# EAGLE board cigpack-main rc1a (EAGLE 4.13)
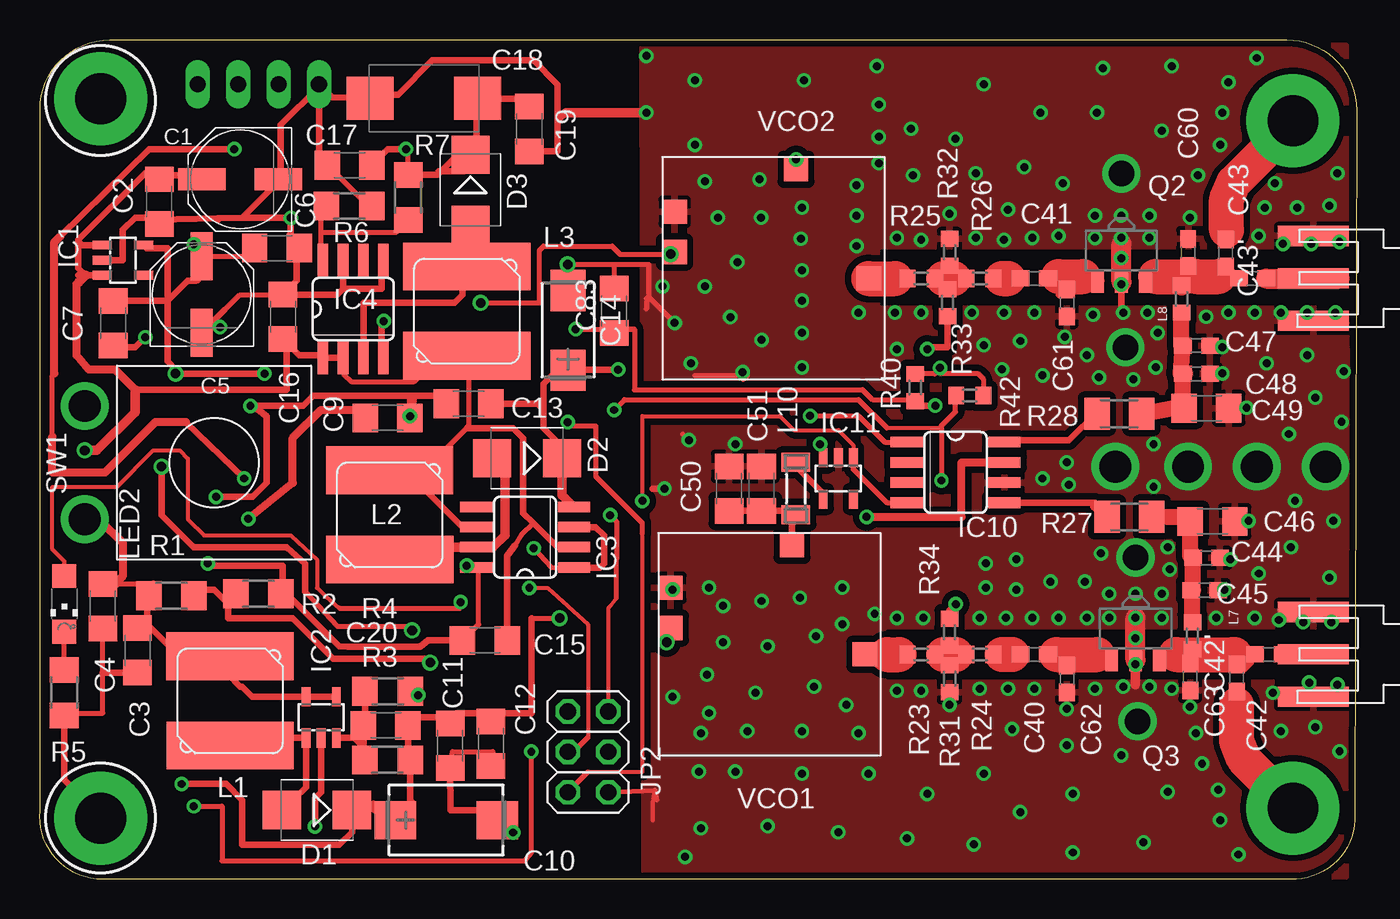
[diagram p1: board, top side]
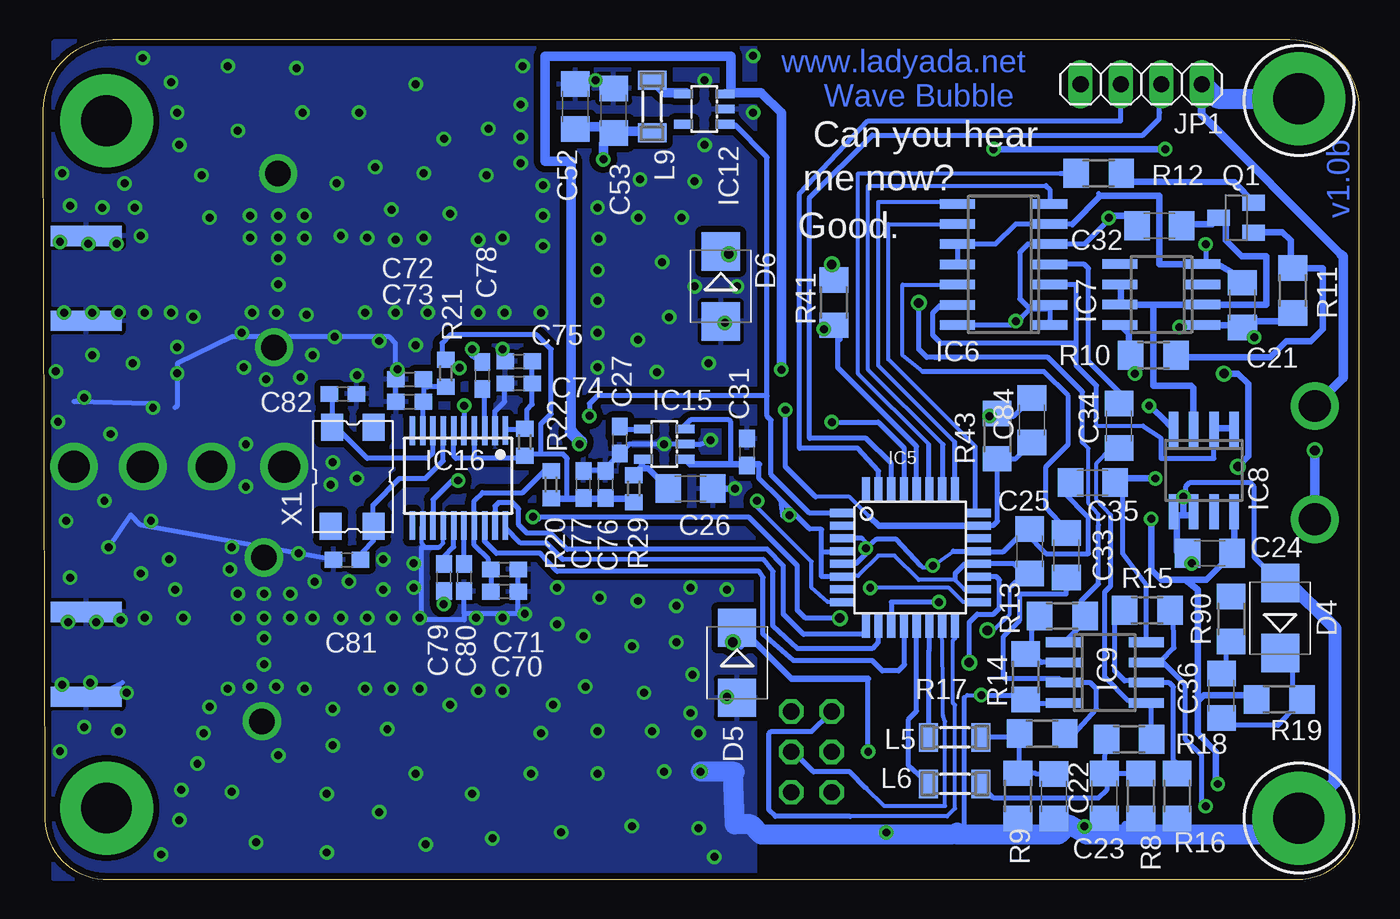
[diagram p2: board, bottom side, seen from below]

Size 82.75 x 52.73 mm. Coordinates in mm from the lower left corner, seen from the top.
Outline: 3.57,0 arc-90 0.02,4.31 0.02,48.34 arc-90 4.4,52.73 78.36,52.73 arc-90 82.75,48.32 82.65,4.08 arc-90 78.96,0 3.57,0
Copper layers (1*16): Top 0.035mm / dielectric 1.5mm / Bottom 0.035mm
Design rules "default": minimum track width 10mil, minimum drill 19mil, track to track 10mil, track to pad 10mil, pad to pad 10mil, via to via 10mil, smd to smd 0mil, copper to edge 10mil, drill to drill 8mil, minimum pad ring 10mil, minimum via ring 8mil, stop-mask expansion 4mil, vias tented up to drill 0mil, thermal gap 10mil

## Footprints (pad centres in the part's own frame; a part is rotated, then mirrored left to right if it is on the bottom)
PANASONIC_D = smd 3 x 1.4: + 2.4,0; - -2.4,0
C1206 = smd 1.6 x 1.8: 1 -1.4,0; 2 1.4,0
CT7343 = smd 2.6 x 2.4: + 3.2,0; - -3.2,0
CT6032 = smd 2.6 x 2.2: + 2.5,0; - -2.5,0
D/7343-31W = smd 2.95 x 2.7: + 3.375,0; - -3.375,0
C0603 = smd 1.1 x 1: 1 -0.85,0; 2 0.85,0
SMB = smd 2.4 x 2.4: A 2.2,0; C -2.2,0
SOT23-5L = smd 0.55 x 1.2: 1 -0.95,-1.3; 2 0,-1.3; 3 0.95,-1.3; 4 0.95,1.3; 5 -0.95,1.3
SO08 = smd 0.66 x 2.032: 1 -1.905,-3.073; 2 -0.635,-3.073; 3 0.635,-3.073; 4 1.905,-3.073; 5 1.905,3.073; 6 0.635,3.073; 7 -0.635,3.073; 8 -1.905,3.073
TQFP32-08 = smd 1.524 x 0.508: 1 -4.293,2.8; 2 -4.293,2; 3 -4.293,1.2; 4 -4.293,0.4; 5 -4.293,-0.4; 6 -4.293,-1.2; 7 -4.293,-2; 8 -4.293,-2.8; 17 4.293,-2.8; 18 4.293,-2; 19 4.293,-1.2; 20 4.293,-0.4; 21 4.293,0.4; 22 4.293,1.2; 23 4.293,2; 24 4.293,2.8 | smd 0.508 x 1.524: 9 -2.8,-4.293; 10 -2,-4.293; 11 -1.2,-4.293; 12 -0.4,-4.293; 13 0.4,-4.293; 14 1.2,-4.293; 15 2,-4.293; 16 2.8,-4.293; 25 2.8,4.293; 26 2,4.293; 27 1.2,4.293; 28 0.4,4.293; 29 -0.4,4.293; 30 -1.2,4.293; 31 -2,4.293; 32 -2.8,4.293
SO14 = smd 0.6 x 2.2: 1 -3.81,-2.9; 2 -2.54,-2.9; 3 -1.27,-2.9; 4 0,-2.9; 5 1.27,-2.9; 6 2.54,-2.9; 7 3.81,-2.9; 8 3.81,2.9; 9 2.54,2.9; 10 1.27,2.9; 11 0,2.9; 12 -1.27,2.9; 13 -2.54,2.9; 14 -3.81,2.9
SO08' = smd 0.6 x 2.2: 1 -1.905,-2.6; 2 -0.635,-2.6; 3 0.635,-2.6; 4 1.905,-2.6; 5 1.905,2.6; 6 0.635,2.6; 7 -0.635,2.6; 8 -1.905,2.6
TSSOP-20 = smd 0.35 x 1.8: 1 -2.835,-3.023; 2 -2.195,-2.999; 3 -1.545,-2.999; 4 -0.895,-2.999; 5 -0.245,-2.999; 6 0.405,-2.999; 7 1.055,-2.999; 8 1.705,-2.999; 9 2.355,-2.999; 10 3.005,-2.999; 11 3.005,2.951; 12 2.355,2.951; 13 1.705,2.951; 14 1.055,2.951; 15 0.405,2.951; 16 -0.245,2.951; 17 -0.895,2.951; 18 -1.545,2.951; 19 -2.195,2.951; 20 -2.845,2.951
1X04 = drill 1.016 long: 1 -3.81,0; 2 -1.27,0; 3 1.27,0; 4 3.81,0
2X03 = drill 1.016 octagon: 1 -2.54,-1.27; 2 -2.54,1.27; 3 0,-1.27; 4 0,1.27; 5 2.54,-1.27; 6 2.54,1.27
CDRH6D28 = smd 3 x 8: L1 -2.8,-0.008; L2 2.8,0.008
SM-1206 = smd 1.2 x 1.8: 1 -1.65,0; 2 1.65,0
0603 = smd 1 x 1.1: 1 -0.875,0.025; 2 0.825,0.025
CHIPLED_1206 = smd 1.5 x 1.5: A 0,-1.75; C 0,1.75
SOT23-BEC = smd 1 x 1.4: B -0.95,-1.1; C 0,1.1; E 0.95,-1.1
SOT89 = smd 0.8 x 1.4: 1 -1.499,-1.981; 2 0,-1.981; 3 1.499,-1.981
R1206 = smd 1.6 x 1.803: 1 -1.422,0; 2 1.422,0
R0603 = smd 1 x 1.1: 1 -0.85,0; 2 0.85,0
M1206 = smd 1.6 x 2: 1 -1.4,0; 2 1.4,0
JUDCOSPST = drill 2 round: P 3.556,-8.128; T -3.556,-8.128
SMA-ANTENNA = smd 1.27 x 4.445: COND 0,-2.794; GND3 -2.667,-2.794; GND4 2.667,-2.794 | smd 1.27 x 4.445 bottom: GND -2.667,-2.794; GND2 2.667,-2.794
MINICIRCUITS_KG = smd 1.524 x 1.524: P$1 3.429,0.762; P$2 5.969,0.762; P$10 7.62,12.954; P$14 0.762,8.382
ABMM = smd 1.7 x 1.4: NC 3.1,-1.3; NC2 -3.1,1.4; X1 -3.1,-1.3; X2 3.1,1.3

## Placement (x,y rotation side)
C1  100uF/6.3  [PANASONIC_D]  12.59,43.97 180 top
C2  .1uF  [C1206]  7.51,42.57 270 top
C3  .1uF  [C1206]  6.14,14.37 270 top
C4  1.0uF  [C1206]  3.97,17.15 270 top
C5  100uF/4V  [PANASONIC_D]  10.18,36.73 90 top
C6  1uF  [C1206]  14.9,39.64 0 top
C7  .1uF  [C1206]  4.61,34.92 270 top
C9  .1uF  [C1206]  21.86,28.98 0 top
C10  100uF/10V  [CT7343]  25.55,3.71 180 top
C11  .1uF  [C1206]  25.79,8.38 270 top
C12  1.0uF  [C1206]  28.35,8.52 270 top
C13  .1uF  [C1206]  26.94,29.87 180 top
C14  68uF/16V  [CT6032]  33.19,34.47 270 top
C15  1.0uF  [C1206]  27.97,15 180 top
C16  .1uF  [C1206]  15.28,35.33 90 top
C17  .1uF  [C1206]  19.47,44.85 180 top
C18  22uF/35V  [D/7343-31W]  24.15,49.05 0 top
C19  1.0uF  [C1206]  30.76,47.13 270 top
C20  160pF  [C1206]  21.75,9.66 180 top
C21  .1uF  [C1206]  7.38,36.07 270 bottom
C22  4.7uF  [C1206]  19.22,5.2 270 bottom
C23  4.7uF  [C1206]  16.05,5.23 270 bottom
C24  .1uF  [C1206]  9.42,20.47 180 bottom
C25  .1uF  [C1206]  20.74,20.59 90 bottom
C26  1.0uF  [C1206]  42.06,24.54 0 bottom
C27  .01uF  [C0603]  46.5,27.58 270 bottom
C31  .1uF  [C0603]  38.5,26.82 90 bottom
C32  .1uF  [C1206]  12.59,41.05 180 bottom
C33  4.7uF  [C1206]  18.43,20.34 270 bottom
C34  4.7uF  [C1206]  15.13,28.47 270 bottom
C35  .1uF  [C1206]  16.78,24.92 180 bottom
C36  .47uF  [C1206]  8.69,11.52 270 bottom
C40  68pF  [C0603]  62.5,14.12 180 top
C41  100pF  [C0603]  62.5,37.74 180 top
C42  68pF  [C0603]  77.23,14.12 180 top
C42'  68pF  [C0603]  75.22,12.65 90 top
C43  100pF  [C0603]  76.22,37.74 180 top
C43'  100pF  [C0603]  74.52,39.33 270 top
C44  1000pF  [C0603]  73.32,20.19 180 top
C45  22pF  [C0603]  73.19,18.16 180 top
C46  .1uF  [C1206]  73.7,22.47 180 top
C47  1000pF  [C0603]  72.68,33.52 180 top
C48  68pF  [C0603]  72.68,31.74 180 top
C49  .1uF  [C1206]  73.32,29.59 180 top
C50  1uF  [C1206]  43.33,24.54 90 top
C51  0.1uF  [C1206]  45.36,24.54 90 top
C52  1uF  [C1206]  49.29,48.54 90 bottom
C53  0.1uF  [C1206]  46.88,48.29 90 bottom
C60  3.9pF  [C0603]  72.16,39.38 90 top
C61  5.6pF  [C0603]  64.54,36.2 270 top
C62  0pF  [C0603]  64.54,12.58 270 top
C63  1.0pF  [C0603]  72.29,12.71 270 top
C70  .01uF  [C0603]  53.74,18.06 0 bottom
C71  100pf  [C0603]  53.74,19.46 0 bottom
C72  100pf  [C0603]  59.71,31.39 180 bottom
C73  .01uF  [C0603]  59.71,30 180 bottom
C74  100pf  [C0603]  52.85,31.14 180 bottom
C75  .01uF  [C0603]  52.85,32.54 180 bottom
C76  .1uF  [C0603]  47.39,24.79 90 bottom
C77  4.7uF  [C0603]  48.79,24.79 90 bottom
C78  100pf  [C0603]  55.14,31.65 270 bottom
C79  100pf  [C0603]  57.55,18.95 90 bottom
C80  100pf  [C0603]  56.28,18.95 270 bottom
C81  20pF  [C0603]  63.64,20.07 180 bottom
C82  20pF  [C0603]  63.89,30.48 0 bottom
C83  0.1uF  [C1206]  36.1,35.7 90 top
C84  0.1uF  [C1206]  20.6,28.84 90 bottom
D1  1N5817  [SMB]  17.42,4.34 180 top
D2  1N5817  [SMB]  30.63,26.44 180 top
D3  1N5817  [SMB]  27.06,43.31 270 top
D4  1N5235  [SMB]  5,16.4 90 bottom
D5  1N5817  [SMB]  39.13,13.59 270 bottom
D6  1N5817  [SMB]  40.15,37.24 270 bottom
IC1  TPS79333  [SOT23-5L]  5.23,38.89 270 top
IC2  LM2733  [SOT23-5L]  17.68,10.17 0 top
IC3  LT1301  [SO08]  30.5,21.49 90 top
IC4  LT1173CS  [SO08]  19.7,35.81 0 top
IC5  ATMEGA48-20A  [TQFP32-08]  28.24,20.21 0 bottom
IC6  AD8402  [SO14]  22.38,38.62 90 bottom
IC7  NE555D  [SO08']  12.46,36.73 90 bottom
IC8  LM358D  [SO08']  9.8,25.68 180 bottom
IC9  LM358D  [SO08']  16.02,12.98 270 bottom
IC10  MIC2506BM  [SO08]  57.55,25.55 270 top
IC11  MIC2514  [SOT23-5L]  50.18,25.17 180 top
IC12  MIC2514  [SOT23-5L]  41.19,48.38 90 bottom
IC15  LP2985  [SOT23-5L]  43.71,27.33 90 bottom
IC16  LMX243X  [TSSOP-20]  56.53,25.17 180 bottom
JP1  [1X04]  13.73,49.94 180 bottom
JP2  [2X03]  34.46,8 270 top
L1  15uH  [CDRH6D28]  11.96,11.2 270 top
L2  33uH  [CDRH6D28]  21.99,22.88 270 top
L3  33uH  [CDRH6D28]  26.84,35.68 90 top
L5  1K  [SM-1206]  25.44,8.91 0 bottom
L6  1K  [SM-1206]  25.44,5.99 0 bottom
L7  22nH  [0603]  72.41,15.27 270 top
L8  33nH  [0603]  71.77,36.47 90 top
L9  0  [SM-1206]  44.47,48.54 90 bottom
L10  0  [SM-1206]  47.52,24.54 270 top
LED2  [CHIPLED_1206]  1.54,17.3 180 top
Q1  3906  [SOT23-BEC]  7.77,41.55 90 bottom
Q2  SXA-389B  [SOT89]  67.97,39.51 0 top
Q3  SXA-389B  [SOT89]  68.86,15.76 0 top
R1  510K  [R1206]  8.27,17.8 180 top
R2  220K  [R1206]  13.73,17.93 180 top
R3  37K  [R1206]  21.86,7.49 0 top
R4  12K  [R1206]  21.86,11.81 180 top
R5  2K  [R1206]  1.54,11.71 270 top
R6  50K  [R1206]  19.44,42.29 180 top
R7  1M  [R1206]  23.16,42.82 90 top
R8  (adj)  [R1206]  13.76,5.23 270 bottom
R9  (adj)  [R1206]  21.48,5.23 270 bottom
R10  10K  [R1206]  12.97,32.92 180 bottom
R11  20K  [R1206]  4.21,36.98 90 bottom
R12  100  [R1206]  16.4,44.35 180 bottom
R13  100K  [R1206]  18.69,16.54 0 bottom
R14  10K  [R1206]  21,12.72 90 bottom
R15  100K  [R1206]  13.35,16.89 0 bottom
R16  10K  [R1206]  11.47,5.23 90 bottom
R17  10K  [R1206]  19.95,9.14 0 bottom
R18  10K  [R1206]  14.5,8.79 0 bottom
R19  2K  [R1206]  5.06,11.29 0 bottom
R20  18  [R0603]  50.82,24.79 90 bottom
R21  18  [R0603]  57.42,31.77 90 bottom
R22  18  [R0603]  52.47,27.46 270 bottom
R23  18  [R0603]  55.39,14.12 180 top
R24  18  [R0603]  59.07,14.12 180 top
R25  18  [R0603]  55.39,37.74 180 top
R26  18  [R0603]  59.07,37.74 180 top
R27  0  [M1206]  68.47,22.76 180 top
R28  0  [M1206]  67.84,29.23 180 top
R29  18  [R0603]  45.61,24.54 270 bottom
R31  0  [R0603]  57.18,12.58 270 top
R32  68  [R0603]  57.18,39.38 90 top
R33  50  [R0603]  57.04,36.22 270 top
R34  50  [R0603]  57.17,15.52 90 top
R40  10k  [R0603]  55.01,30.89 270 top
R41  10k  [R1206]  33.04,36.22 90 bottom
R42  10k  [R0603]  58.44,30.38 180 top
R43  10k  [R1206]  22.78,27.83 270 bottom
R90  100K  [R1206]  8.08,16.34 270 bottom
SW1  SPST  [JUDCOSPST]  10.95,26.17 270 top
U$8  SMAANTENNA  [SMA-ANTENNA]  82.82,37.74 270 top
U$9  SMAANTENNA  [SMA-ANTENNA]  82.82,14.12 270 top
VCO1  ROS2500  [MINICIRCUITS_KG]  38.88,21.74 270 top
VCO2  ROS1200  [MINICIRCUITS_KG]  39.13,45.36 270 top
X1  10.000 MHz  [ABMM]  63.27,25.28 90 bottom

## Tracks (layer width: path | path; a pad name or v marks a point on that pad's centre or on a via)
+6V  (via drill 0.5, 0.6)
  Top 0.305: 30.89,16.39 v32.67,16.39 | 28.86,10.42 28.73,10.04 28.61,10.17 C12.1 | 25.43,10.17 25.56,10.04 25.66,10.17 C11.1 | 23.08,10.23 23.02,10.3 C20.1
  Top 0.406: 30.89,16.39 30.89,10.42 28.86,10.42 26.19,10.42 | 26.19,10.42 25.43,10.17 23.27,10.17 23.08,10.23 23.02,10.17 | 25.92,9.9 25.81,9.92 26.19,10.42 | C20.1 23.15,8.13 23.27,8.01 23.28,8.02 R3.2 23.28,4.97 23.27,4.96 23.36,4.87 C10.+ 20.24,4.72 20.98,4.71 20.97,4.72 D1.C 19.62,2.96 18.82,2.17 12.73,2.17 12.73,4.96 11.71,5.98 v8.92,5.98 | C9.1 20.48,28.97 | C9.1 | 19.7,29.49 19.95,29.49 C9.1
  Top 0.508: v13.1,22.63 15.9,24.9 15.9,27.72 17.67,29.49 19.7,29.49 | IC10.7 57.93,26.19 57.93,22.76 v51.96,22.76
  Top 0.61: C9.1 | C9.1 20.97,28.47 | C9.1 20.21,29.23
  Bottom 0.305: 51.58,22.63 51.83,22.63 51.95,22.74 | 51.95,22.74 v51.96,22.76 | 51.95,22.74 38.38,22.74 35.33,19.69 35.33,16.9 34.83,16.39 v32.67,16.39
  Bottom 0.406: v51.96,22.76 51.96,22.5 | 9.81,11.57 7.1,11.57 R19.1 6.61,11.67 6.63,11.69 6.89,11.44 | 9.81,11.57 10.19,11.31 10.19,18.17 10.95,18.81 | 10.95,18.81 12.47,18.81 13.11,19.44 13.11,21.37 v13.1,22.63 | 8.02,20.44 7.89,20.32 | 8.02,20.44 C24.1 | 7.89,20.32 IC8.8 | 7.89,20.32 7.78,20.2 | 8.02,20.44 9.65,18.81 10.95,18.81 | v8.92,5.98 9.05,5.98 9.05,8.01 10.19,9.15 10.19,11.19 9.81,11.57
+12V  (via drill 0.5)
  Top 0.305: IC11.3 49.17,26.4 v49.04,27.33
  Top 0.406: 32.95,26.57 D2.C 32.83,27.16 31.65,28.33 31.65,29.47 | 28.85,30.25 28.72,30.12 28.47,30.12 | 28.47,30.12 28.34,30.12 | 28.47,30.12 28.47,30.25 | C13.1 28.47,29.99 28.47,30.12 | 28.34,29.98 28.35,29.98 | C13.1 28.34,29.98 | 28.34,29.98 28.22,29.98 | v36.35,32.01 34.57,32.01 32.67,31.99 32.56,31.89 | C13.1 28.45,29.98 | 32.56,31.89 32.41,31.89 31.65,31.12 31.65,29.47 | C14.+ 33.11,31.89 32.56,31.89 | C13.1 28.35,29.86 28.35,29.85 31.27,29.85 31.65,29.47
  Top 0.61: IC3.4 33.55,23.39 32.83,24.11 D2.C
  Bottom 0.61: 49.56,28.08 49.56,45.09 51.21,45.09 51.21,51.7 39.53,51.7 39.53,49.33 IC12.3 39.73,49.33 39.65,49.41 37.62,49.41 36.35,48.14 v36.35,32.01
  Bottom 0.813: 49.56,28.08 48.94,27.46 v49.04,27.33
+24V  (via drill 0.5)
  Top 0.305: C17.1 21.5,45.47 21.63,45.6 | v23.02,45.86 23.12,45.6 R7.2 | 0.92,31.76 0.79,31.63 0.79,27.82
  Top 0.406: v12.85,25.17 9.18,28.71 | 1.29,40.39 6.89,45.86 v12.22,45.86 | R7.2 25.01,44.24 25.14,44.37 | C17.1 20.87,44.95 | 21.5,45.47 21.49,45.48 21.87,45.86 v23.02,45.86 | 21.5,45.47 | 25.14,44.37 27.46,46.69 27.46,48.98 C18.+ 27.51,49.03 | 27.51,49.03 27.33,49.03 | C19.1 30.26,49.03 27.51,49.03 | 25.14,44.37 25.05,44.46 26.65,44.46 D3.C
  Top 0.508: 1.29,40.39 0.92,40.01 0.92,31.76 | 0.79,27.82 0.79,25.54 4.09,25.54 7.27,28.71 9.18,28.71
  Bottom 0.305: IC9.8 13.42,18.48 14.89,20.46 14.89,25.17 15.4,24.9 15.63,24.66 C35.1
  Bottom 0.406: 14.89,25.17 v12.85,25.17 | v12.22,45.86 v23.02,45.86
CLK
  Bottom 0.254: 24.16,27.19 29.62,32.65 29.62,41.16 IC6.9
  Bottom 0.305: IC5.24 24.16,23.21 24.16,27.19
CP_IF  (via drill 0.5)
  Top 0.305: R40.2 55.01,30.12 52.34,30.12 51.71,30.76 37.37,30.74 37.37,34.55 | v33.68,34.55 37.37,34.55 | 37.37,34.55 36.1,34.55 C83.1
  Top 0.406: 55.01,30.12 55.39,29.74 v56.28,29.74
  Bottom 0.305: IC16.5 v56.29,29.73 v56.28,29.74 | IC5.28 27.84,27.19 32.79,32.14 32.79,34.43 32.66,33.91 R41.1 32.67,34.43 32.67,34.55 v33.68,34.55
CP_RF  (via drill 0.5)
  Top 0.254: 53.23,28.35 56.66,28.35
  Top 0.305: v56.66,25.04 56.66,28.35 56.66,28.47 57.55,29.36 57.55,30.38 | 57.55,30.38 57.42,30.38 | 53.23,28.35 51.45,30.12 36.75,30.12 v36.1,29.47 | 57.55,30.38 R42.2
  Bottom 0.254: 30.79,22.74 32.06,24.01 34.19,24.01
  Bottom 0.305: IC16.13 58.24,23.85 57.04,25.04 v56.66,25.04 | IC5.23 23.05,22.2 22.76,22.49 22.76,24.27 22.78,25.01 R43.2 22.76,26.43 21.62,26.43 C84.1 | 34.19,24.01 36.1,25.92 v36.1,29.47
  Bottom 0.406: IC5.23 30.22,22.2 30.79,22.74
FB
  Top 0.305: IC4.8 17.68,39 17.68,40.65 | R6.2 17.68,42.2 17.68,40.65 | R7.1 22.41,40.65 17.68,40.65
GND  (via drill 0.5, 0.6, 1.6, 2, 3.2 pad 5.84)
  Top 0.254: IC3.8 26.69,19.71 | 38.64,5.6 38.51,4.84 38.51,3.69
  Top 0.305: 38.27,36.58 v39.9,34.95 40.15,34.95 | IC3.8 26.69,19.58 | VCO2.P$1 39.77,41.81 | 33.57,22.22 33.67,22.12 | 33.57,22.22 IC3.3 33.59,22.11 | 33.57,22.22 33.55,22.25 | 39.64,17.93 VCO1.P$1 v39.77,18.19 | 44.21,31.39 44.47,31.65 41.17,31.65 | U$8.GND4 79.39,35.08 | v40.79,27.58 40.4,27.96 | 38.12,35.81 38.12,36.47 38.25,36.6 | 20.98,42.43 | 20.98,42.43 R6.1 | C17.2 20.5,42.43 20.98,42.43 | C16.2 15.3,36.71 15.4,36.71 12.56,36.71 11.59,35.73 | IC3.8 26.97,19.58 26.95,19.57 v26.83,19.69 | C9.2 23.27,28.97 23.14,28.84 v23.27,29.09 | IC3.1 32.16,19.57 v31.04,20.79 | 21.49,34.93 21.62,34.81 v21.62,35.06 | 38.76,4.96 38.64,5.6 35.74,5.47 JP2.6 | 38.25,36.6 38.26,36.59 | v33.18,38.62 36.1,38.62 | 36.1,38.62 38.26,38.62 38.25,36.6 | C11.2 25.93,8.01 28.47,8.01 C12.2 | C4.2 3.97,12.96 3.97,10.42 1.55,10.42 1.55,10.3 R5.2 | IC3.8 27.44,19.57 27.59,19.57 27.59,16.01 C15.2 | 36.1,38.62 C83.2
  Top 0.406: 27.55,19.46 IC3.8 27.45,19.56 27.45,19.46 | 33.67,22.12 33.8,22 | 39.64,42.06 39.77,42.06 VCO2.P$1 | IC1.2 5.23,38.89 5.23,40.79 5.99,41.55 6.75,41.55 7.26,41.43 | 7.26,41.43 7.32,41.49 | 7.32,41.49 7.38,41.42 | 11.2,41.52 7.26,41.43 | 12.72,41.55 11.2,41.52 | 12.72,41.55 15.39,44.22 C1.- 15.1,44.08 15.14,44.08 15.14,47.38 17.55,49.79 | v39.26,24.54 38.5,24.54 | 7.32,41.49 7.38,41.55 7.38,41.68 C2.2 | 23.26,30.38 C9.2 | 23.26,30.38 25.55,30.38 C13.2 25.68,29.73 25.68,29.6 | 23.4,30.36 17.17,30.36 16.54,29.73 v13.24,29.73 13.3,29.79 14.25,29.09 14.25,24.9 13.36,24.01 v11.08,24.01 | 23.4,30.36 23.65,30.36 | 23.26,30.38 23.37,30.24 23.4,30.36 | 11.2,41.52 11.2,41.41 | 11.59,35.73 C5.- 9.81,34.33 10.16,34.68 v11.33,34.68 | 12.72,41.55 12.73,41.54 v15.78,41.54 15.78,40.17 C6.2 16.19,39.76 16.16,39.76 16.16,37.6 C16.2 15.27,36.71 | IC4.4 21.49,32.85 21.49,34.93 21.75,35.19 | IC4.7 19.08,38.87 19.08,37.09 | 19.08,37.09 21.49,37.09 21.49,39 | 21.49,39 | 21.49,39 IC4.5 | 15.27,36.71 15.14,36.71 | 19.08,37.09 18.7,36.71 15.4,36.71 15.27,36.71 | 17.55,49.79 17.55,49.93 JP1.4 18.36,49.11 C18.- 20.6,49.22 20.6,49.29 22.51,49.29 24.67,51.44 31.02,51.44 32.54,49.92 32.54,47.63 | C17.2 17.55,45.37 17.55,49.79 | v10.56,19.84 10.56,19.69 15.26,19.69 15.26,17.75 15.39,17.55 15.64,17.55 15.16,17.53 R2.1 15.4,17.41 15.91,17.54 18.82,14.62 19.33,14.61 23.9,14.61 24.41,15 C15.2 | v68.09,35.58 67.96,35.83 67.97,35.82 Q2.2 | v3.84,3.82 3.84,3.95 1.54,6.24 R5.2 | v17.3,3.31 17.3,5.09 17.68,5.47 IC2.2 | R4.1 23.66,11.81 v23.78,11.57 | v29.75,2.93 29.76,2.95 C10.- 28.49,4.34 28.73,4.33 25.82,4.31 C11.2
  Top 0.406: C7.2 4.72,33.41 6,33.41 v6.63,34.05 | C19.2 32.54,45.73 32.54,47.63 | C14.- 32.95,37.22 32.79,37.22 33.05,37.47 33.05,38.62 v33.18,38.62 | IC3.3 34.94,22.12 35.46,21.6 35.46,19.82 35.21,19.57 33.56,19.57 IC3.1 | IC3.1 | 32.54,47.63 33.06,48.16 | C3.2 3.97,12.96
  Top 0.61: 23.39,30.12 C9.2 | 68.86,12.2 Q3.2 | 33.06,48.16 v38.12,48.16
  Top 1.27: Q3.2 68.86,16.39 | Q2.2 67.97,39.89
  Bottom 0.254: IC16.14 57.59,21.11 57.84,20.85 58.69,20.85 58.95,21.11 58.95,22.16 IC16.12 58.89,22.25 | v26.83,19.69 25.53,20.6 | 27.59,19.69 27.46,19.57 26.95,19.57 | 31.27,21.4 31.02,21.15 v31.04,20.79 | 25.17,3.18 24.84,3.29 | 24.84,11.41 24.67,11.57 v23.78,11.57
  Bottom 0.305: D6.A 40.15,34.95 v39.9,34.95 | U$8.GND4 80.54,35.2 v78,35.58 | v78.12,39.9 U$8.GND | U$9.GND4 79.65,11.45 79.77,11.33 77.74,12.34 | 60.6,30 C73.2 60.69,30.12 | C72.2 60.6,31.35 60.6,30 | C71.2 52.89,18.1 52.85,18.06 C70.2 52.89,16.66 52.6,16.66 | v80.16,30.25 80.79,30 75.97,29.87 | v78.63,20.85 77.23,22.88 76.6,22.25 C81.2 | 60.6,30 60.6,33.68 60.98,34.06 70.88,34.06 74.31,32.41 74.31,29.74 74.44,29.62 | 52.22,16.66 v52.47,16.66 52.6,16.66 | 56.28,16.66 C80.2 | 52.6,16.66 56.28,16.66 | 57.84,20.85 58.95,20.85 58.95,16.28 56.28,16.28 56.28,16.66 | 47.43,25.68 C76.2 | C77.2 48.75,25.68 47.43,25.68 | v40.79,27.58 41.42,27.33 IC15.2 45.9,27.33 C27.2 46.5,26.69 47.43,25.77 47.43,25.68 | IC16.2 54.34,29.4 53.74,30 53.74,31.14 C74.2 | C75.2 53.7,32.62 53.87,32.79 v53.87,33.3 | 18.72,34.91 18.82,34.81 IC6.1 19.46,34.81 19.33,34.93 19.48,35.08 19.48,35.97 19.59,36.08 IC6.2 19.46,36.08 19.71,35.82 20.73,35.82 | 19.46,39.89 17.3,39.89 15.52,41.67 | IC9.4 18.64,11.06 20.51,11.06 R14.1 21.52,11.57 v23.78,11.57 23.65,11.69 | C24.2 10.7,20.58 10.57,20.58 | 11.33,3.69 11.35,3.68 R16.1 | 11.33,3.69 11.44,3.8 | C23.2 16.79,3.83 16.79,3.82 16.78,3.8 | C23.2 16.55,3.83 16.54,3.82 16.56,3.8 | 18.32,3.44 18.32,3.69 18.18,3.83 | 20.73,35.82 21.36,36.46 21.36,39.38 20.86,39.89 19.46,39.89 | 19.46,39.89 IC6.5 | 20.98,21.73 21.24,21.73 22.38,20.58 23.97,20.58 | 20.98,21.73 20.76,21.73 C25.2 21,21.74 20.98,21.73 | 23.97,20.58 24.16,20.58 | 23.97,20.58 IC5.21 25.53,20.6 | C35.2 18.56,24.26 17.05,22.74 17.05,20.46 19.71,20.46 20.98,21.73 | v23.27,29.09 22.67,29.13 R43.1 22.76,29.24 22.76,29.09 21.75,29.09 C84.2
  Bottom 0.305: 31.27,21.4 IC5.3 | IC5.5 32.29,19.82 31.65,19.82 31.02,20.46 v31.04,20.79 30.38,21.35 29.11,21.35 27.59,19.69 | 26.83,19.57 v26.83,19.69 26.95,19.57 | 20.73,35.82 21.75,34.81 | 21.75,34.81 IC6.14 | 21.75,34.81 21.62,34.93 v21.62,35.06 | 38.26,3.44 38.39,3.58 | 11.33,3.69 11.2,3.57 11.2,2.8 | 15.27,2.8 15.27,3.06 15.28,3.06 | 15.28,3.06 C23.2 | 14.89,3.18 14.89,3.06 15.28,3.06 | 18.44,3.31 18.57,3.44 18.85,3.44 C22.2 | 21.75,2.68 21.75,2.8 21.75,3.55 R9.2 | 24.84,3.29 24.84,11.41 | R41.2 32.96,37.26 v33.18,38.62 | D4.A 6.63,20.24 6.63,24.65 6.89,24.9 10.7,24.9 10.95,24.65 10.95,24.01 v11.08,24.01
  Bottom 0.406: C26.2 v39.26,24.54 | 17.93,50.44 17.8,50.44 JP1.4 | 9.88,34.81 9.93,34.81 | 9.88,34.81 IC7.1 9.85,34.81 9.55,34.81 | 9.55,34.81 8.41,34.81 | 6.76,35.06 C21.2 7.24,34.81 | R11.1 4.47,35.06 6.76,35.06 | 6.76,35.06 6.89,35.06 6.63,35.32 v6.63,34.05 | C32.2 14.61,41.67 15.52,41.67 15.65,41.67 v15.78,41.54 | 7.24,34.81 7.14,34.81 | 7.24,34.81 9.55,34.81 | 9.55,34.81 9.88,34.81 | IC8.6 10.57,22.94 10.57,22.87 11.08,22.87 | 11.49,22.87 IC8.5 11.59,22.96 | 11.08,22.87 11.49,22.87 | IC8.4 12.47,29.05 v13.24,29.73 | 11.33,20.84 11.33,20.71 | 11.33,20.84 11.33,20.99 | C24.2 10.57,20.22 | 4.09,4.2 3.84,3.95 v3.84,3.82 | 25.3,2.8 25.17,3.18 | 25.3,2.93 24.92,2.93 | 24.92,2.93 25.17,2.93 | 25.17,3.18 24.92,2.93 | 25.17,3.18 24.79,2.8 25.68,2.8 | v11.33,34.68 11.2,34.81 9.55,34.81 | C24.2 10.82,20.58 11.49,20.58 | 11.49,22.87 11.49,20.58 | 11.33,20.84 11.2,20.84 | 11.49,20.58 11.49,20.84 11.33,20.84 | C24.2 10.82,20.33 10.56,20.33 v10.56,19.84 | v11.08,24.01 11.08,22.87 | 14.76,3.31 14.63,3.18 | 14.89,3.18 14.76,3.31 | 14.76,3.31 14.76,3.44 | R8.2 14.27,3.8 14.76,3.31 | 18.44,3.31 v17.3,3.31 | 29.62,2.8 v29.75,2.93
  Bottom 0.508: 17.8,50.44 17.8,50.57
  Bottom 0.813: 3.97,3.57 3.84,3.69 v3.84,3.82 1.54,6.12 1.54,15.75 4.6,18.81 4.6,18.93 4.93,18.6 D4.A
  Bottom 1.27: v3.84,3.82 5.11,3.44 5.74,2.8 11.2,2.8 15.27,2.8 17.17,2.8 18.32,3.44 18.44,3.31 18.95,2.8 21.75,2.8 24.79,2.8 25.3,2.8 25.3,2.93 25.68,2.8 29.62,2.8 37.62,2.8 38.26,3.44 39.27,3.44 39.4,6.74 39.28,6.74 v41.42,6.76
  other vias: 78.89,23.77 41.55,9.17 39.77,11.46 42.06,10.44 41.93,12.85 44.47,9.3 47.9,9.3 48.66,12.09 50.69,10.95 50.44,16.03 50.44,18.31 48.79,15.27 45.74,14.63 44.98,11.71 42.94,14.88 42.94,17.17 45.36,17.47 47.77,17.68 40.56,1.4 42.06,18.31 64.53,8.41 81.81,28.73 70.12,32.16 54.76,47.14 78,9.3 80.16,9.55 60.72,16.41 81.04,18.95 81.3,22.5 62.38,16.41 78.5,27.96 51.45,9.17 47.9,32.16 47.9,36.35 47.82,40.23 45.36,33.88 39.13,37.24 43.83,38.76 45.33,41.55 41.8,37.24 45.23,43.97 47.9,38.25 43.4,35.31 42.61,41.55 47.9,34.32 41.8,43.84 47.9,42.19 40.91,32.41 69.74,41.68 76.98,42.19 79.65,32.92 66.82,50.95 51.33,39.78 51.45,35.59 51.33,41.68 52.6,51.08 74.69,50.06 74.31,48.16 74.19,46.13 72.79,44.22 81.04,42.32 71.14,51.08 44.16,31.85 41.55,3.2 43.71,6.76 51.33,43.59 48.02,50.19 70,24.66 64.41,34.06 59.33,33.55 81.55,44.35 54.88,44.22 60.85,42.06 58.82,44.35 57.55,46.51 62.88,48.16 61.87,44.73 66.44,48.16 47.9,6.63 45.74,3.33 50.18,2.95 52.09,6.63 54.5,2.56 59.33,6.63 75.33,1.55 70.88,5.49 64.92,1.68 81.68,8.03 64.92,5.36 61.11,9.42 61.61,4.22 55.77,5.36 58.69,2.18 76.47,51.59 76.6,40.41 77.62,43.71 64.28,43.71 79.9,39.9 79.65,35.59 81.43,35.59 81.68,40.03 65.8,32.92 74.31,33.43 61.61,33.81 60.47,32.03 65.8,16.41 66.69,20.47 64.03,16.41 59.07,16.41 43.71,27.33 79.39,16.15 81.17,16.15 76.6,19.2 64.53,26.19 79.77,12.34 81.55,12.22 57.17,41.81 53.87,40.28 55.39,40.16 58.82,40.28 60.6,40.16 62.38,40.28 58.57,35.59 53.74,35.59 55.39,35.59 60.6,35.59 62.5,35.59 64.03,40.41 66.31,40.28 67.96,40.28 69.74,40.28 67.96,37.36 67.96,39.01 72.28,41.55 79.01,42.19 68.73,31.39 66.19,35.46 69.61,35.59 70.25,34.32 74.69,35.59 76.35,35.59 77.11,32.41 74.31,31.77 75.84,29.62 66.57,31.52 67.96,41.68 66.31,41.68 74.44,18.19 74.82,20.09 75.96,22.5 67.2,16.41 68.85,17.93 68.85,16.41 70.5,16.41 73.93,16.41 76.35,16.41 77.87,16.28 60.85,11.96 62.5,11.96 66.31,11.96 64.53,10.69 59.07,11.96 68.09,12.09 69.74,12.09 71.14,11.96 57.17,10.95 55.39,11.84 53.87,11.84 53.87,16.41 55.52,16.41 72.28,10.82 77.49,11.71 72.66,9.17 73.04,7.26 74.06,5.61 74.19,3.71 67.96,7.77 69.36,2.31 80.8,25.92 76.48,25.92 72.16,25.92 67.59,25.92 59.45,18.31 59.45,19.84 70,27.33 61.36,20.09 61.36,18.19 65.68,18.69 70.88,20.85 71.01,19.46 81.93,31.9 52.72,44.98 52.72,46.63 52.72,48.67 38.12,51.71 41.17,50.19 67.2,17.93 70.5,17.93 68.85,15.14 68.85,13.49 68.86,20.2 68.99,9.92 68.23,33.41 67.97,44.33 70.5,47.02 59.33,49.94 41.17,46.13 73.3,35.33 63.01,25.17 63.01,31.65 63.52,18.69 64.66,24.79
  pour Top (isolate 0.406): 37.86,52.48 82.06,52.35 82.06,39.76 52.61,39.76 52.61,35.82 82.07,35.82 82.45,15.88 52.99,15.88 52.99,12.33 82.06,12.33 82.06,0.15 37.99,0.28
  pour Bottom (isolate 0.406): 37.99,0.28 37.99,52.73 82.06,52.6 82.06,0.03
LBI  (via drill 0.6)
  Top 0.406: 11.83,17.3 11.93,17.19 R2.2 11.85,17.68 | 11.83,17.3 11.83,16.53 11.84,16.39 15.9,16.39 18.44,13.85 24.29,13.85 v24.54,13.6 | R1.1 9.71,18.17 10.96,18.17 11.83,17.3
  Bottom 0.305: v24.54,13.6 24.54,16.14 24.03,16.65 23.02,16.65 22.63,17.03 22.63,18.81 22.83,19 IC5.19
MISO
  Bottom 0.254: 25.43,15.88 25.43,15.12 25.56,15 25.56,11.06 25.43,10.93 25.43,4.45 25.94,3.95 32.03,3.95
  Bottom 0.305: 33.07,10.17 33.07,10.55 33.05,10.55 33.06,10.54 JP2.1 33.18,10.52 33.18,10.42 33.3,10.42 34.45,9.28 36.99,9.28 37.11,9.15 37.11,4.33 36.73,3.95 32.03,3.95 | IC5.16 25.43,15.9 25.43,15.88
N$1
  Bottom 0.254: 19.71,43.57 30.89,43.57 30.89,32.01 26.19,27.31
  Bottom 0.305: IC6.7 19.48,43.34 19.71,43.57 | IC5.26 26.22,24.52 26.19,24.52 26.19,27.31
N$2
  Top 0.406: 11.83,7.14 11.71,7.26 L1.L2 11.58,7.26 12.91,8.59 | 12.91,8.59 13.1,8.79 | 12.91,8.59 12.86,8.65 13.08,8.87 IC2.1 16.73,6.42 16.74,5.78 D1.A | 12.91,8.59
N$3  (via drill 0.5)
  Top 0.254: 1.54,19.83 LED2.A 1.54,19.07 1.43,19.19 1.55,19.95 0.79,20.71 0.79,24.65 4.85,24.65 7.14,26.93 8.79,26.93 9.3,26.43 9.3,22.62 10.32,21.6 15.78,21.6 17.43,20.08 17.43,18.3 17.94,17.79 18.82,17.03
  Top 0.305: v26.44,17.41 26.44,17.03 18.82,17.03
  Bottom 0.305: IC5.11 29.44,17.41 v26.44,17.41
N$5
  Bottom 0.305: D4.C 4.22,13.43 4.22,11.69 4.09,11.57 4.09,11.49 R19.2 5.14,9.66 8.63,9.66 | 8.63,9.66 8.92,9.92 | 8.63,9.66 C36.2
N$6  (via drill 0.5)
  Top 0.406: v55.77,33.3 55.91,33.41 57.04,33.41 R33.2
  Bottom 0.305: C78.1 55.35,32.5 55.77,32.92
  Bottom 0.406: v55.77,33.3 55.77,32.92 55.64,33.04
N$7
  Bottom 0.305: 27.07,8.78 27.21,8.9 | 27.07,8.78 L5.1 27.08,8.9 27.21,9.15 27.08,9.41 27.08,14.32 27.04,14.36 IC5.14 | 26.7,9.53 27.04,9.57 27.07,8.78
N$8  (via drill 0.5)
  Top 0.305: v48.41,29.11 51.45,29.11 53.1,27.46 IC10.1
  Bottom 0.305: v48.41,29.11 48.41,29.87 47.91,30.36 37.24,30.36 | 37.24,30.36 37.24,45.35 39.27,47.38 39.94,47.38 | 37.24,30.36 37.24,29.09 36.99,28.84 36.99,25.41 34.57,23 32.53,23 | 32.53,23 32.29,23 | IC5.1 32.53,23 | 39.94,47.38 40.16,47.38 | 39.94,47.38 IC12.1
N$9
  Bottom 0.305: L6.1 28.35,7.12 28.35,10.04 27.84,10.55 IC5.13
N$10
  Top 0.61: L2.L2 21.74,19.72 21.86,19.84 24.53,19.84 25.42,20.85 IC3.7 28.35,20.84 28.45,20.84 29.23,21.61 29.23,25.64 D2.A
N$11
  Bottom 0.406: Q1.B 6.38,40.32 6.05,40.65 4.85,40.65 4.35,40.14 4.35,38.36 4.42,38.36 | R10.1 11.92,32.78 5.62,32.78 4.6,33.79 3.08,33.79 2.31,34.55 2.31,38.36 4.42,38.36 | 4.42,38.36 R11.2
N$12
  Bottom 0.406: C32.1 11.2,41.06 11.2,41.16 9.26,41.16 Q1.C 8.75,41.67 8.41,41.67 8.41,40.14 7.39,39.13 5.87,39.13 5.87,36.08 12.47,36.08 | IC7.2 9.88,36.08 12.47,36.08 | 12.98,36.08 12.47,36.08 | 12.98,36.08 15.05,36.08 IC7.7 15.01,36.14 15.01,37.31 IC7.6 | 12.98,36.08 12.98,31 10.57,31 10.44,30.87 10.44,28.29 IC8.3
N$13
  Bottom 0.406: Q1.E 7.85,43.77 12.47,43.82 14.25,43.82 14.78,44.35 R12.1
N$14
  Top 0.305: C41.1 64.37,37.98 64.04,37.86
  Top 0.406: 66.65,37.65 66.7,37.6 | 66.65,37.65 Q2.1 | 65.56,37.86 66.45,37.86 66.65,37.65 | C61.1 64.42,36.71 64.04,36.71 64.04,37.86 C61.1
  Top 2.184: 64.04,37.86 65.56,37.86
N$15
  Bottom 0.254: 16.54,28.97 16.54,28.46 13.62,28.46
  Bottom 0.305: IC6.3 17.81,37.35 17.81,33.66 | IC8.2 9.16,26.43 12.47,26.43 12.47,27.7 13.62,28.46 | IC6.13 26.32,36.08 26.83,35.57 26.83,34.17 26.32,33.66 17.81,33.66 | 17.81,33.66 17.81,32.27 16.54,31 16.54,28.97
  Bottom 0.406: IC8.1 7.9,28.29 7.9,28.33 9.11,28.33 IC8.2
N$16
  Bottom 0.305: R17.2 17.95,9.14 16.54,10.68 16.54,11.95 16.92,12.33 18.57,12.33 18.59,12.34 IC9.3 18.86,12.58 22.25,12.58 22.38,12.71 22.38,15.25 21.36,16.27 21.36,17.92 18.44,17.92 18.43,18.18 C33.2
N$17
  Top 0.406: C40.1 63.35,14.11 63.91,14.11 | 66.45,14.11 64.8,13.98 64.54,13.98 C62.1
  Top 0.61: Q3.1 66.65,13.9 66.45,14.11
  Top 2.184: 63.91,14.11 66.45,14.11
N$18
  Bottom 0.305: 21.24,14.74 21.27,14.78 R14.2 | R14.2 21.33,14.78 20.86,14.23 19.98,13.61 IC9.2 | R14.2 20.62,14.09 20.62,15.62 R13.1
N$19
  Top 0.406: IC4.3 20.35,32.76 20.35,36.2 26.06,36.2 26.57,36.71 26.57,38.62 26.69,38.62 L3.L2
  Top 0.61: L3.L2 26.71,38.36 26.44,38.36 26.44,40.49 D3.A
N$20  (via drill 0.5)
  Top 0.254: v30.76,18.3 31.91,18.3 34.45,16.01 34.45,8.9
  Top 0.305: JP2.3 33.2,8.01 33.56,8.01 34.45,8.9
  Bottom 0.254: IC5.17 24.92,17.4 25.81,18.3 v30.76,18.3
N$21
  Bottom 0.254: IC6.12 28.73,37.35 28.73,32.9 27.46,31.89
  Bottom 0.305: IC6.12 25.17,37.35 | C33.1 18.46,22 18.44,21.98 19.71,23.38 19.71,25.92 18.32,27.31 18.32,30.36 19.84,31.89 27.46,31.89
N$22
  Bottom 0.305: 13.24,12.46 13.35,12.34 IC9.6 | 13.24,12.46 13.11,12.33 11.97,12.33 11.71,12.07 11.71,6.87 10.95,6.99 | 10.95,6.99 11.59,7.38 | 11.73,6.47 11.08,6.36 | R16.2 11.73,6.47 | 10.95,6.99 11.33,6.87 11.73,6.47 | 13.24,12.46 14.76,12.46 15.4,13.09 15.4,16.27 R15.1 | R15.1
N$23
  Top 0.406: 47.64,26.19 L10.1 47.52,25.93 49.23,24.22 IC11.4
N$24
  Bottom 0.305: IC6.4 17.3,38.62 17.05,38.36 17.05,32.52 15.01,30.49 15.01,30.24 15.13,30.12 C34.1
N$25  (via drill 0.5)
  Top 0.406: R34.2 57.17,16.89 v57.56,17.28
  Bottom 0.406: 57.55,17.54 57.55,17.3 | 57.55,17.54 C79.1 | 57.55,17.54 57.56,17.54 v57.56,17.28
N$26
  Top 1.016: R27.1 70.89,22.74 72.3,22.74 C46.2 72.3,20.33 | 72.3,20.33 72.47,20.33 C44.2 72.47,18.17 72.43,18.17 | 72.3,20.33 72.42,20.46 | C45.2 72.34,18.17 72.43,18.17 | L7.1 72.43,18.17
N$27
  Top 0.406: 60.6,27.46 IC10.8 60.98,27.58 64.69,27.58 65.43,28.33 R28.2
N$28
  Bottom 0.254: 15.64,27.07 16.54,26.12 16.54,23.83 15.65,22.87
  Bottom 0.305: 13.22,9.17 13.24,9.15 | R18.2 13.22,9.17 | 13.22,9.17 13.11,9.28 13.11,10.76 IC9.5 14.51,11.19 16.03,12.71 16.03,18.04 15.65,18.42 15.65,22.87 | 15.64,27.07 C34.2
N$29
  Top 0.406: C51.1 C50.1 | C51.1 45.48,23.14 | L10.2 | C51.1 47.52,23.14 L10.2 | L10.2 47.26,22.89 VCO1.P$14
N$30  (via drill 0.5)
  Top 0.61: VCO2.P$14 47.53,44.59 | VCO2.P$14 | VCO2.P$14 v47.53,45.22
  Bottom 0.61: C52.1 49.3,47.25 47.25,47.25 C53.1 | C53.1 47.53,46.24 v47.53,45.22 | L9.1 44.58,47 46.77,47 C53.1
N$31
  Bottom 0.305: R90.2 8.38,15.12 8.41,15.12 8.41,12.81 C36.1
N$32
  Top 1.016: R28.1 70.63,29.49 71.9,29.73 71.92,29.73 C49.2 71.92,29.47 | L8.1 71.75,33.41 71.83,33.41 C47.2 71.71,31.76 | 71.71,31.76 71.96,31.76 C48.2 71.83,29.73 71.92,29.47 | 71.71,31.76 71.78,31.76 | 71.92,29.47 71.91,29.47
N$33
  Bottom 0.61: 42.41,49.41 42.32,49.41 | IC12.4 42.41,49.41 | L9.2 43.69,49.41 42.41,49.41
N$34
  Bottom 0.254: IC5.15 26.19,12.46 26.19,10.3 26.06,9.92 26.06,4.58 29.87,4.58 31.02,5.72
  Bottom 0.305: 31.02,5.72 32.03,6.74 34.32,6.74 35.59,8.01 35.72,8.01 JP2.4
N$35
  Bottom 0.305: IC16.8 58.24,26.77 58.57,26.44 62.38,26.44 64.52,28.58 64.54,28.58 | 64.65,28.58 64.67,28.58 | 64.65,28.58 X1.X2 64.54,28.54 64.54,28.58 | 64.54,28.58 64.65,28.58 | C82.1 64.54,30.28 64.54,28.58
N$35R
  Top 0.406: C43.2 74.48,37.98 74.3,37.93 | 74.07,37.86 74.3,37.93 | 72.04,37.86 71.28,37.47 | 71.28,37.47 C60.1 | 74.3,37.93 74.3,37.88 74.32,37.86 74.52,38.05 C43'.2 | Q2.3 69.47,37.5 69.37,37.47 70.13,37.86 | 71.28,37.47 71.4,37.47 71.53,37.6 71.66,37.73 | 72.67,37.86 72.55,37.86 72.38,37.69 L8.2
  Top 1.27: 71.53,37.6 72,37.73 L8.2
  Top 2.184: 70.13,37.86 72.04,37.86 | 72.67,37.86 74.07,37.86
N$37
  Bottom 0.305: C80.1 56.28,19.96 56.29,19.97 IC16.16
N$39
  Bottom 0.305: IC15.4 45.07,28.22 46.63,28.22 46.5,28.35 C27.1 46.5,28.47
N$40  (via drill 0.5)
  Top 0.305: R42.1 59.29,31.43 58.95,31.77 56.57,31.77 56.57,31.99 56.53,32.03 56.57,32.07 v56.57,32.12 | v56.57,32.12 56.53,32.08 | 56.62,32.12 56.66,32.16 | v56.57,32.12 56.62,32.12 | R40.1 56.24,31.74 56.62,32.12
  Bottom 0.305: R20.1 49.8,23.94 49.8,26.44 50.06,26.69 51.45,26.69 | IC16.6 56.94,26.59 56.79,26.44 55.77,26.44 55.71,26.5 | 55.71,26.5 55.64,26.44 52.09,26.44 52.22,26.57 | IC16.4 55.64,26.57 55.71,26.5 | 51.45,26.69 52.22,26.69 | 51.45,26.69 51.45,28.6 50.82,29.23 50.82,33.3 51.71,34.19 57.17,34.19 57.68,33.68 57.68,32.79 57.51,32.62 R21.2 57.26,32.62 56.66,32.03 v56.57,32.12
  Bottom 0.406: 47.43,23.9 47.52,23.9 | R29.2 45.83,23.9 47.43,23.9 | 47.43,23.9 C76.1 | 47.43,23.9 48.79,23.9 C77.1 48.83,23.9 50.86,23.9 | 50.86,23.9 50.95,23.9 | 50.86,23.9 R20.1 | 52.3,26.61 R22.2 | 52.22,26.69 52.3,26.61 | 52.3,26.61 52.25,26.61 52.22,26.57
N$41
  Top 0.406: R23.2 53.89,14.12 54,14.11 | 51.7,14.12 51.59,14.23 | VCO1.P$10 51.7,14.12 | 53.24,14.11 51.97,14.11 51.7,14.12
  Top 2.184: 53.24,14.11 54,14.11
N$42
  Top 0.406: R24.1 60.43,14.16 61.12,14.11 | C40.2 61.51,14.38 61.12,14.11 | 60.48,14.11 60.61,13.34 61.12,14.11
  Top 2.184: 61.12,14.11 60.48,14.11
N$43
  Top 0.406: 72.31,14.23 72.42,14.23 | L7.2 72.31,14.23 | 72.31,14.23 72.31,14.74 72.16,14.74 72.16,14.36 72.31,14.36 72.31,14.23 | 72.31,14.23 71.42,14.11 | C42.2 76.38,14.23 76.1,14.23 76.1,13.6 75.98,13.6 C42'.2 75.98,13.47 | 75.98,13.47 75.72,13.22 | C63.1 73.56,13.98 75.09,14.11 | 74.96,14.11 74.96,14.23 75.98,14.23 75.98,13.47
  Top 0.61: L7.2 72.43,14.38 71.86,14.41 Q3.3
  Top 2.184: 71.42,14.11 74.96,14.11 75.09,14.11
N$45
  Bottom 0.254: 18.82,44.33 31.52,44.33 31.52,31.76 27.08,27.31
  Bottom 0.305: R12.2 18.46,44.35 18.82,44.33 | IC5.27 27.08,24.53 27.08,27.31
N$46
  Bottom 0.305: C78.2 55.14,30.63 55.01,30.76 54.99,30.74 IC16.3
N$47
  Top 0.305: R25.2 53.75,37.73
  Top 2.184: VCO2.P$10 53.75,37.73
N$49
  Top 0.406: 60.56,38.49 60.48,37.73 R26.1 | C41.2 61.78,37.73 60.86,37.73
  Top 2.184: 60.48,37.73 60.86,37.73
N$52
  Bottom 0.305: IC16.15 56.94,20.88 57.55,20.27 C79.2
N$57  (via drill 3.2 pad 5.84)
  Bottom 0.508: 1.16,39.27 1.19,39.27 9.93,48.02 9.93,49.92 JP1.1
  Bottom 0.61: 1.19,39.27 1.04,39.13 1.04,31.51 SW1.T
  Bottom 1.27: JP1.1 9.82,49.94 8.92,49.03 v3.84,49.03
N$58
  Top 0.406: R27.2 66.21,23.39 66.58,23.5 66.31,23.65 IC10.5
N$60
  Top 0.305: 1.54,13.1 R5.1 1.47,13.13 | 1.47,13.13 1.43,13.09 | LED2.C 1.54,13.21 1.47,13.13
N$664  (via drill 0.5)
  Top 0.254: 51.13,25.74 51.13,27.26 50.19,28.2 47.4,28.2 46.51,29.09 37.87,29.09 v37.87,23.76
  Top 0.305: 51.13,25.74 IC11.1 | IC10.4 53.23,23.65 51.13,25.74 | 51.13,25.74 51.84,25.03
  Bottom 0.254: v37.87,23.76 37.87,23.38 34.45,19.95 34.45,18.3 33.43,17.41 32.67,17.41 32.66,17.4 IC5.8
N$666
  Bottom 0.305: IC16.7 57.59,26.27 58.69,25.17 60.34,25.17 62,23.5 62,22.74 61.88,22.62 61.97,22.52 X1.X1 61.97,21.25 62.64,20.58 62.64,20.08 62.65,20.07 C81.1
N$10077
  Bottom 0.305: IC16.1 53.67,28.22 52.3,28.22 | C75.1 52,31.18 51.96,31.14 C74.1 52,29.83 52.34,29.49 52.34,28.47 52.47,28.35 R22.1
  Bottom 0.406: 52.3,28.22 52.22,28.22 52.3,28.31 R22.1
PLL_CLK
  Bottom 0.305: IC16.19 54.34,23.43 54.12,23.65 53.23,23.65 52.85,23.27 52.85,22.25 52.34,21.74 50.84,21.74 49.81,20.71 37.23,20.73 36.22,19.69 36.22,16.65 34.95,15.38 31.02,15.38 31.02,15.89 IC5.9
PLL_DATA
  Bottom 0.305: IC16.20 53.69,22.07 52.72,21.11 51.1,21.11 50.07,20.08 37.48,20.09 36.86,19.34 36.86,15.88 35.33,14.49 30.64,14.49 30.25,14.91 IC5.10
PLL_LE
  Bottom 0.305: 55.01,22 54.99,22.02 | 55.01,22 55.01,21.23 54.25,20.47 51.48,20.47 51.46,20.46 50.44,19.33 37.74,19.33 37.49,18.96 37.49,15.38 35.59,13.73 30.64,13.73 30,13.09 28.98,13.09 28.6,13.47 28.6,15.88 IC5.12 | 55.01,22 55.01,22.12 54.99,22.14 IC16.18
RESET  (via drill 0.5)
  Top 0.254: 37.87,21.73 37.87,6.74 34.45,6.74
  Top 0.305: v33.18,28.71 33.43,28.46 34.95,28.46 34.95,25.28 37.87,22.36 37.87,21.73 | 33.18,5.45 33.18,5.34 | JP2.5 33.18,5.45 | 34.45,6.74 33.18,5.47 33.18,5.45
  Bottom 0.305: IC5.29 28.64,27.1 30.25,28.71 v33.18,28.71
RF_OUT
  Top 0.305: U$8.COND 81.04,37.74
  Top 1.27: U$8.COND 81.68,37.73 C43.1
RF_OUT1
  Top 0.406: 80.03,14.11 80.04,14.11 | 80.03,14.11 U$9.COND | C42.1 78.08,14.11 80.03,14.11
RX
  Bottom 0.305: JP1.2 12.59,49.94 12.59,48.16 12.6,47.77 13.62,46.75 30.64,46.75 34.57,42.81 34.57,27.7 31.02,27.7 29.44,26.12 IC5.30
SDI
  Bottom 0.254: 25.44,27.46 30.25,32.27 30.25,42.55 25.56,42.55
  Bottom 0.305: IC5.25 25.44,27.46 | IC6.8 25.43,42.43 25.56,42.55
SENSE
  Top 0.406: IC2.3 19.74,8.87 20.48,8.14 | R4.2 20.44,10.38 20.35,10.29 C20.2 20.35,8.65 20.35,8.26 20.48,8.14 | 20.48,8.14 20.47,8.13 R3.1
STRIPLINE1  (via drill 3.2 pad 5.84)
  Top 0.406: C42'.1 75.22,10.93 75.21,10.93
  Top 2.184: v78.76,4.47 v78.75,4.47 75.68,7.54 75.21,8.67 75.21,10.93
STRIPLINE2  (via drill 3.2 pad 5.84)
  Top 0.406: C43'.1 74.52,40.78 74.58,40.78
  Top 1.016: 76.09,44.42 76.39,45.17 v78.76,47.65
  Top 2.184: v78.76,47.65 78.76,47.5 75.03,43.76 74.58,42.68 74.58,40.78
TX
  Bottom 0.305: IC5.31 30.24,25.65 31.52,27.06 35.21,27.06 35.21,43.06 30.89,47.63 15.01,47.63 15,49.8 JP1.3 14.99,49.92 14.89,49.92
VCC  (via drill 0.5, 0.6)
  Top 0.254: JP2.2 35.73,17.02 35.84,17.15 36.22,17.66
  Top 0.305: 9.67,38.89 9.8,38.76 9.8,39.77 v9.68,39.89 | C5.+ 10.06,39.13 | C5.+ | 13.11,39.25 12.98,39.13 C5.+ | 13.11,39.25 13.24,39.38 | 12.98,39.38 | 13.11,39.25 12.98,39.38 | C6.1 13.24,39.38 12.98,39.38 | 36.22,17.66 36.23,22.48 v35.84,22.87 | 16.67,18.04 18.7,15.88 23.4,15.88 v23.4,15.63
  Top 0.406: IC1.5 6.71,39.65 8.03,39.65 8.03,36.46 | 9.67,38.12 9.67,37.87 | 9.67,38.12 9.8,38.12 9.8,37.73 9.87,37.66 | 9.87,37.66 9.91,37.62 | 9.67,38.12 9.8,38.25 9.8,38.76 9.8,39.01 C5.+ | C7.1 4.61,36.33 8.03,36.33 | 8.03,36.46 8.03,36.33 | v14.13,31.76 8.79,31.76 8.54,32.01 | 9.87,37.66 9.81,37.6 9.3,37.6 8.03,36.33 | 8.54,32.01 8.03,32.52 8.03,36.46 | 16.67,18.04 16.67,19.82 15.52,20.84 9.68,20.84 7.65,22.87 v7.65,25.92 | v8.54,31.76 8.54,32.01
  Bottom 0.254: 24.83,18.2 25.43,18.81 27.71,18.81 29.24,20.33 30.25,20.33 31.52,19.06 32.54,19.06 IC5.6 | 21.87,18.42 22,18.3 22,16.65 22.89,15.76 v23.4,15.63
  Bottom 0.305: 39.52,26.06 39.52,28.73 39.64,28.85 42.06,28.85 42.56,28.35 42.44,28.22 42.44,28.25 IC15.3 | C31.1 38.08,25.97 37.99,26.06 | 25.17,38.62 IC6.11 25.43,38.62 25.28,38.77 IC6.10 | IC6.10 22.89,39.89 21.62,41.16 19.59,41.16 | 19.33,41.16 IC6.6 19.59,41.16 | IC7.8 15.06,34.76 | 19.59,41.16 18.06,41.16 16.54,42.68 | IC7.4 9.44,38.63 9.43,38.62 9.68,38.87 v9.68,39.89 | 14.39,33.01 14.38,33.03 | 14.39,33.01 R10.2 | v14.13,31.76 14.76,32.65 14.39,33.01 | 25.17,40.01 25.28,39.91 IC6.10 | 16.28,42.94 16.41,43.06 | 23.9,18.17 IC5.18 | IC5.18 23.92,18.17 | 24.03,18.2 24.03,18.3 | 24.03,18.2 IC5.18 | 24.03,18.2 24.03,18.17 | 36.4,23.83 34.57,22.01 33.81,21.98 33.81,20.58 | 36.4,23.83 36.48,23.89 37.74,25.15 37.74,26.06 | IC5.4 32.54,20.58 33.81,20.58 | IC5.6 33.81,19 33.81,20.58 | 24.83,18.2 24.03,18.2 | 36.27,22.82 36.1,22.87 | 36.4,23.83 36.27,22.82 | 36.27,22.82 v35.84,22.87 | 25.43,18.81 25.43,19.19 24.81,19.8 IC5.20 21.73,19.8 21.11,19.19 21.1,19.19 C25.1 21.01,18.68 21.62,18.68 21.87,18.42
  Bottom 0.406: IC15.1 42.09,26.06 39.52,26.06 37.99,26.06 37.74,26.06 | R10.2 14.54,32.78 14.51,32.78 14.51,34.26 IC7.8 15.06,34.81 | C21.1 7.26,37.35 7.14,37.86 7.39,37.74 8.92,38.62 9.43,38.62 9.85,38.62 IC7.4 9.88,38.62 12.6,38.62 12.6,42.94 16.28,42.94 18.06,41.16 | v7.65,25.92 7.01,26.55 7.01,31.12 7.65,31.76 v8.54,31.76
VCC1
  Bottom 0.305: 58.82,31.27 58.82,30.04 C73.1 58.82,30 | 58.82,31.27 58.82,31.39 C72.1 58.86,31.31 58.82,31.27 | R21.1 58.6,30.92 58.6,31.05 58.82,31.27 | 58.82,30 58.69,30.12 | IC16.9 58.89,29.93 58.82,30
VCC2
  Bottom 0.305: 54.59,19.16 C71.1 54.63,19.46 | 54.59,19.16 C70.1 | R20.2 50.86,25.68 51.2,25.68 52.6,24.28 55.14,24.28 55.64,23.77 IC16.17 55.64,20.98 54.76,20.09 54.76,19.33 54.63,19.46 | 54.59,19.16 54.59,19.42 54.63,19.46
VCO1_DCADJ
  Bottom 0.305: C23.1 16.17,6.6 16.05,7.23 R18.1 | 14.27,6.63 R8.1 | 14.27,6.63 C23.1 | 14.27,6.63 14.25,6.61 | L6.2 23.79,5.87 23.02,5.09 16.41,5.09 15.9,5.6 15.9,6.36 16.05,6.5 C23.1
VCO1_OUT
  Top 0.406: R23.1 57.04,13.99 56.8,14.11 | R24.2 58.31,14.12 58.32,14.11 57.56,14.11 | R34.1 57.17,14.5 57.56,14.11 | R31.1 57.18,13.47 57.05,13.6 57.56,14.11
  Top 2.184: 57.56,14.11 56.8,14.11
VCO1_TUNE  (via drill 0.5, 0.6)
  Top 0.305: v9.68,4.58 11.46,4.58 11.46,1.15 30.51,1.15 30.89,1.66 v30.89,8.01
  Top 0.406: 39.64,15.65 VCO1.P$2 39.39,15.52 v39.39,14.88 39.26,15.01
  Bottom 0.254: D5.C 38.88,14.63 v39.39,14.88
  Bottom 0.305: R15.2 11.83,16.89 11.71,16.77 11.67,14.53 12.47,13.73 13.36,13.73 13.42,13.67 IC9.7 12.36,13.61 10.95,12.2 10.95,8.77 9.93,7.76 9.93,4.58 v9.68,4.58 | v30.89,8.01 30.89,12.58
  Bottom 0.406: v39.39,14.88 39.64,15.14 | 38.88,14.63 38.51,15 38.13,15 35.72,12.58 30.89,12.58
VCO2_DCADJ
  Bottom 0.305: C22.1 20.34,6.6 20.39,6.65 R9.1 22.17,6.65 22.13,6.61 21.37,7.37 R17.1 21.5,9.14 21.74,8.91 L5.2
VCO2_OUT
  Top 0.305: R25.1 56.8,37.73 | 57.81,37.98 57.18,37.73 | R32.1 57.43,37.98 57.43,37.73 57.3,37.73 R33.1
  Top 0.406: 57.81,37.98 57.81,37.86 58.22,37.86 R26.2
  Top 2.184: 56.8,37.73 57.18,37.73 57.43,37.73
VCO2_TUNE  (via drill 0.6)
  Top 0.305: 39.64,39.14 39.65,39.13 | 39.64,39.14 v39.64,39.27 | 39.64,39.14 39.53,39.25 36.48,39.25 35.97,39.76 31.65,39.76 31.4,39.51 31.4,36.2 v27.71,36.2
  Top 0.406: VCO2.P$2 39.77,39.27 v39.64,39.27
  Bottom 0.254: 16.41,22.23 16.41,22.92 17.05,23.61 17.05,27.06 17.43,27.44
  Bottom 0.305: 18.32,14.87 18.33,14.88 IC9.1 18.59,14.88 18.57,14.87 17.77,15.67 R13.2 17.52,17.44 16.41,18.55 16.41,22.23 | v39.64,39.27 39.5,39.13 | 17.43,27.44 17.43,30.62 19.59,32.78 26.57,32.78 | 26.57,32.78 26.7,32.78 | v27.71,36.2 27.71,33.28 27.21,32.78 26.57,32.78
  Bottom 0.406: D6.C 39.98,39.27 v39.64,39.27
VIN  (via drill 0.6)
  Top 0.305: IC4.2 19.06,32.76 19.08,32.78 19.08,31.76 19.59,31.25 23.52,31.25 23.9,31.63 26.95,31.63 26.95,28.46 26.89,28.39 23.54,25.05 23.27,25.05 L2.L1 | 4.73,18.55 | C4.1 4.73,18.55 | 4.73,18.55 7.14,18.55 | 29.87,20.96 30.25,21.6 31.02,22.36
  Top 0.406: 8.78,44.22 6.62,44.35 2.43,40.16 2.43,39.9 | 8.78,44.22 C1.+ 10.56,44.22 | 2.43,39.9 2.43,38.38 2.87,37.94 | 2.87,37.94 2.43,37.94 | 2.87,37.94 IC1.3 | 2.43,39.9 2.56,39.9 2.62,39.84 IC1.1 | C2.1 7.51,44.22 8.78,44.22 | IC2.4 16.82,11.47 16.79,11.44 16.76,11.47 IC2.5 13.33,11.47 12.71,12.09 12.59,12.09 11.82,12.86 L1.L1 10.68,13.75 8.02,14.76 6.89,15.88 6.25,15.88 C3.1 6.76,16.39 6.76,18.28 | IC4.1 17.65,32.74 17.68,32.78 17.72,32.74 IC4.1 | IC4.1 IC4.2 | IC4.1 17.68,32.85 17.68,32.9 16.31,32.9 C16.1 15.52,33.69 15.52,30.74 6,30.74 | 23.27,25.05 23.78,24.9 26.56,22.12 IC3.6 | IC3.2 32.53,20.85 31.02,22.36 30.38,23 30.38,27.7 29.75,28.33 26.95,28.33 26.89,28.39 | L3.L1 26.87,32.9 26.95,32.9 26.95,31.63 | C15.1 29.37,16.52 29.37,20.33 29.87,20.96 | 6.76,18.28 6.76,18.3 7.14,18.42 7.14,18.55 | 6.76,18.28 R1.2
  Top 0.508: 6,30.74 4.73,32.01 3.08,32.01 2.31,32.9 2.31,37.38 2.44,37.5 | 4.73,18.55 5.24,19.06 5.24,21.09 3.84,22.49 2.95,22.49 SW1.P
  Top 0.61: C1.+ 10.94,43.97 | C4.1 4.73,18.55 | 2.44,37.5 2.87,37.94 | 6,30.74 6,29.35 3.58,26.93 v2.82,26.93
  Bottom 0.61: SW1.P v2.82,26.93
VPP
  Bottom 0.305: IC15.5 45.07,26.31 45.1,26.31
  Bottom 0.406: 45.21,25.79 45.1,25.89 45.1,26.31 45.1,26.41 | 45.21,25.79 R29.1 | 45.21,25.79 45.23,25.81 44.73,25.81 C26.1

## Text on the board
Bottom: www.ladyada.net | Wave Bubble | v1.0b
bPlace: Can you hear | me now? | Good.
